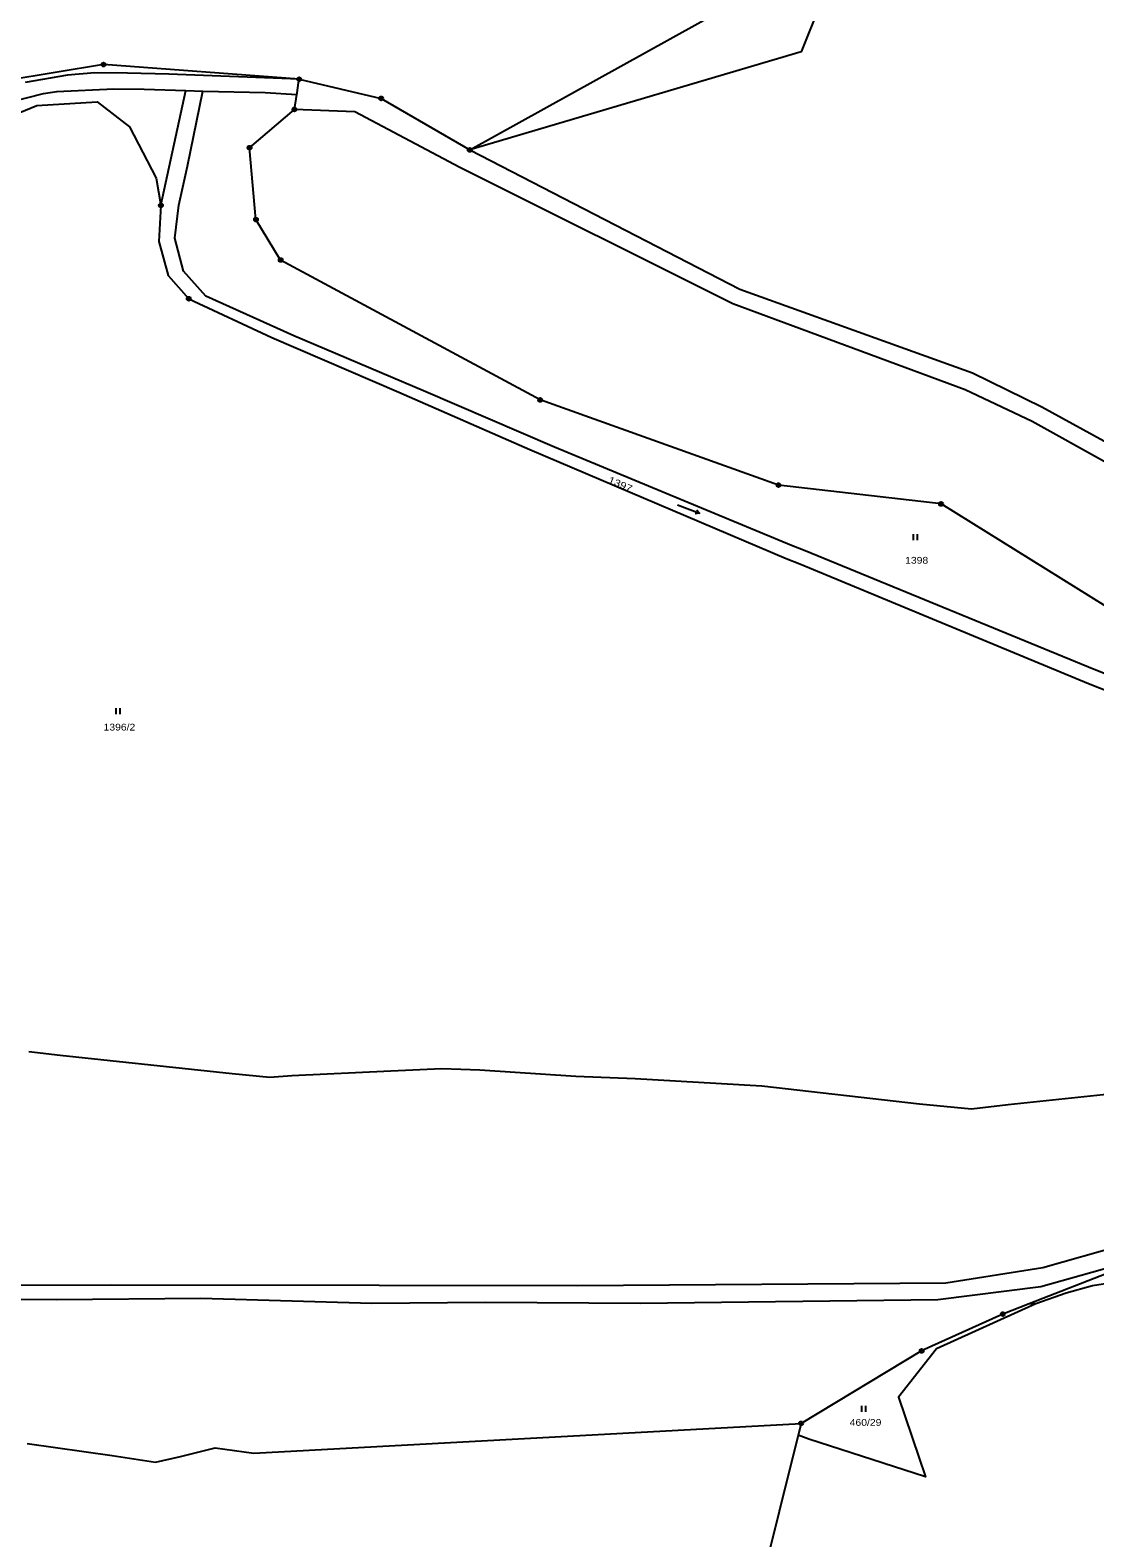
# Model space of a CAD drawing. Extents: x -872229 to -869198, y -1075981 to -1074329.
# Drawn here: x -870040 to -869771.9, y -1075317.7 to -1074938.2 of the extents above; entities that cross this region are included whole.
import ezdxf

# ---------------------------------------------------------------- set-up
doc = ezdxf.new("R2010")
doc.units = 0
doc.header["$LTSCALE"] = 0.68
for name, color, linetype, lineweight in [('1', 7, 'Continuous', 25), ('3', 7, 'Continuous', 25), ('8', 7, 'Continuous', 25)]:
    doc.layers.add(name, color=color, linetype=linetype, lineweight=lineweight)
doc.layers.add('2', color=7, linetype='Continuous')

msp = doc.modelspace()

# ---------------------------------------------------------------- linework, layer by layer
at = {"layer": '1'}
for p, q in [((-870000.81, -1074953.44), (-869996.55, -1074953.58)), ((-869973.47, -1074958.19), (-869972.88, -1074954.43)), ((-869786.75, -1075258.83), (-869788.46, -1075258.83))]:
    msp.add_line(p, q, dxfattribs=at)
for points in [[(-869929.31, -1074968.38), (-869859.5, -1074929.56), (-869836.07, -1074859.72), (-869814.43, -1074830.62), (-869841.11, -1074822.59), (-869856.86, -1074756.63), (-869872.29, -1074734.28)], [(-869776.86, -1074851.73), (-869795.77, -1074853.27), (-869831.49, -1074907.84), (-869845.83, -1074943.67), (-869929.31, -1074968.38)], [(-869972.29, -1074950.57), (-870021.54, -1074946.89), (-870070.32, -1074954.92), (-870080.13, -1074961.97), (-870086.48, -1074985.27), (-870095.97, -1074990.9), (-870107.93, -1074988.38), (-870115.36, -1074981.96)], [(-869972.29, -1074950.57), (-870005.11, -1074949.31), (-870015.47, -1074949.04), (-870023.75, -1074949), (-870030.59, -1074949.58), (-870041.3, -1074951.38)], [(-870192.71, -1075015.36), (-870177.13, -1075014.56), (-870131.91, -1075008.73), (-870095.14, -1075003.44), (-870085.27, -1074997.72), (-870068.68, -1074975.81), (-870058.23, -1074965.32), (-870038.32, -1074957.19), (-870023.13, -1074956.23), (-870015.04, -1074962.59), (-870008.3, -1074975.45), (-870007.09, -1074982.34), (-870000.81, -1074953.44)], [(-870048.94, -1074957.25), (-870036.64, -1074954.16), (-870033.32, -1074953.66), (-870018.94, -1074952.97), (-870011.33, -1074953.07), (-870000.81, -1074953.44)], [(-869650.14, -1075156.59), (-869663.85, -1075147.72), (-869682.43, -1075136.12), (-869690.84, -1075131.53), (-869772.1, -1075099.13), (-869844.86, -1075069.32), (-869848.3, -1075067.94), (-869907.96, -1075043.15), (-869940.96, -1075028.98), (-869973.59, -1075015.13), (-869995.78, -1075005.14), (-870001.42, -1074998.91), (-870003.58, -1074990.56), (-870002.58, -1074982.27), (-870000.39, -1074972.48), (-869996.55, -1074953.58)], [(-869996.55, -1074953.58), (-869980.83, -1074953.94), (-869972.88, -1074954.43)], [(-869972.88, -1074954.43), (-869972.82, -1074954.01), (-869972.43, -1074951.5), (-869972.29, -1074950.57)], [(-869972.29, -1074950.57), (-869951.64, -1074955.4), (-869929.31, -1074968.38)], [(-869646.48, -1075133.71), (-869717.21, -1075097.82), (-869761.54, -1075087.98), (-869810.64, -1075057.49), (-869851.57, -1075052.75), (-869911.59, -1075031.3), (-869976.94, -1074996.08), (-869983.15, -1074985.9), (-869984.78, -1074967.82), (-869973.47, -1074958.19)], [(-869479.66, -1075070.06), (-869480.79, -1075070.33), (-869510.31, -1075083.29), (-869563.58, -1075099.14), (-869607.33, -1075104.27), (-869641.09, -1075105.05), (-869657.9, -1075102.95), (-869677.61, -1075097.87), (-869787.66, -1075036.73), (-869804.59, -1075028.78), (-869863.04, -1075007.07), (-869931.86, -1074972.77), (-869958.29, -1074958.82), (-869973.47, -1074958.19)], [(-869929.31, -1074968.38), (-869861.33, -1075003.43), (-869802.73, -1075024.51), (-869785.27, -1075033.02), (-869675.06, -1075093.42), (-869657.01, -1075098.88), (-869640.84, -1075100.95), (-869607.45, -1075100.23), (-869563.99, -1075095.38), (-869511.48, -1075079.68), (-869481.91, -1075066.7), (-869467.98, -1075063.1), (-869463.59, -1075063.5)], [(-870007.09, -1074982.34), (-870007.65, -1074991.46), (-870005.25, -1074999.97), (-870000.07, -1075005.82), (-869979.18, -1075015.56), (-869947.14, -1075029.34), (-869914.15, -1075043.78), (-869849.68, -1075071.21), (-869846.22, -1075072.58), (-869773.51, -1075102.64), (-869692.27, -1075134.64), (-869683.71, -1075138.39), (-869669.29, -1075147.62), (-869665.53, -1075150.2), (-869650.68, -1075159.97)], [(-869656.67, -1075197.48), (-869676.11, -1075198.92), (-869705.7, -1075200.11), (-869719.96, -1075200.44), (-869741.96, -1075203.08), (-869769.79, -1075206.17), (-869793.73, -1075208.74), (-869802.97, -1075209.8), (-869816.06, -1075208.55), (-869855.81, -1075204.07), (-869887.65, -1075202.22), (-869902.63, -1075201.56), (-869926.76, -1075200.04), (-869936.33, -1075199.65), (-869949.18, -1075200.24), (-869974.1, -1075201.42), (-869979.65, -1075201.82), (-869989.18, -1075200.96), (-870032.43, -1075196.35), (-870040.36, -1075195.42)], [(-870385.12, -1075316.07), (-870355.23, -1075301.89), (-870314.21, -1075282.93), (-870280.58, -1075266.36), (-870265.86, -1075261.9), (-870249.15, -1075258.69), (-870230, -1075254.57), (-870219.5, -1075254.87), (-870207.6, -1075253.65), (-870190, -1075251.81), (-870178.96, -1075255.5), (-870167.23, -1075255.17), (-870141.46, -1075254.46), (-870092.41, -1075254.3), (-870019.81, -1075254.06), (-869952.16, -1075254.08), (-869902.23, -1075254.21), (-869809.43, -1075253.56), (-869784.98, -1075249.67), (-869765.49, -1075244.15), (-869696.7, -1075225.43), (-869659.27, -1075213.75)], [(-870086.74, -1075257.68), (-870033.35, -1075257.7), (-869997.08, -1075257.38), (-869953.96, -1075258.61), (-869925.38, -1075258.43), (-869886.31, -1075258.63), (-869811.48, -1075257.76), (-869785.54, -1075254.45), (-869749.68, -1075244.36), (-869718.38, -1075235.81), (-869677.56, -1075222.96), (-869659.87, -1075217.53)], [(-869709.56, -1075239.45), (-869765.65, -1075249.96), (-869788.46, -1075258.83)], [(-869684.1, -1075246.72), (-869694.41, -1075248.14), (-869706.94, -1075248.13), (-869726.28, -1075244.45), (-869746.39, -1075250.29), (-869772.5, -1075254.32), (-869779.17, -1075256.14), (-869786.75, -1075258.83)], [(-869786.75, -1075258.83), (-869811.82, -1075270.12), (-869821.36, -1075282.34), (-869814.57, -1075302.35), (-869843.97, -1075292.89), (-869846.6, -1075291.84), (-869856.2, -1075330.32)], [(-869788.46, -1075258.83), (-869795.08, -1075261.41), (-869815.52, -1075270.65), (-869845.88, -1075288.92), (-869846.6, -1075291.84)], [(-870040.81, -1075293.97), (-870019.39, -1075297.01), (-870008.45, -1075298.66), (-870002.2, -1075297.21), (-869993.42, -1075295.03), (-869983.72, -1075296.42), (-869845.88, -1075288.92)]]:
    msp.add_lwpolyline(points, dxfattribs=at)
at = {"layer": '3'}
for p, q in [((-869871.436, -1075059.839), (-869872.528, -1075059.957)), ((-869817.551, -1075066.62), (-869817.551, -1075065.12)), ((-869816.55, -1075066.62), (-869816.55, -1075065.12)), ((-870018.391, -1075110.42), (-870018.391, -1075108.92)), ((-870017.39, -1075110.42), (-870017.39, -1075108.92)), ((-869830.621, -1075286.01), (-869830.621, -1075284.51)), ((-869829.62, -1075286.01), (-869829.62, -1075284.51))]:
    msp.add_line(p, q, dxfattribs=at)
msp.add_lwpolyline([(-869877.038, -1075057.689), (-869871.436, -1075059.839), (-869872.169, -1075059.021)], dxfattribs=at)
at = {"layer": '8'}
for centre, radius in [((-870021.54, -1074946.8899), 0.5), ((-870021.54, -1074946.8899), 0.0303), ((-869972.29, -1074950.5699), 0.5), ((-869972.29, -1074950.5699), 0.0303), ((-869973.47, -1074958.1899), 0.5), ((-869951.64, -1074955.3999), 0.5), ((-869951.64, -1074955.3999), 0.0303), ((-869973.47, -1074958.1899), 0.0303), ((-869984.78, -1074967.8199), 0.5), ((-869984.78, -1074967.8199), 0.0303), ((-869929.31, -1074968.3799), 0.5), ((-869929.31, -1074968.3799), 0.0303), ((-870007.09, -1074982.3399), 0.5), ((-870007.09, -1074982.3399), 0.0303), ((-869983.15, -1074985.8999), 0.5), ((-869983.15, -1074985.8999), 0.0303), ((-869976.94, -1074996.0799), 0.5), ((-869976.94, -1074996.0799), 0.0303), ((-870000.07, -1075005.8199), 0.5), ((-870000.07, -1075005.8199), 0.0303), ((-869911.59, -1075031.2999), 0.5), ((-869911.59, -1075031.2999), 0.0303), ((-869851.57, -1075052.7499), 0.5), ((-869851.57, -1075052.7499), 0.0303), ((-869810.64, -1075057.4899), 0.5), ((-869810.64, -1075057.4899), 0.0303), ((-869795.08, -1075261.4099), 0.5), ((-869795.08, -1075261.4099), 0.0303), ((-869815.52, -1075270.6499), 0.5), ((-869815.52, -1075270.6499), 0.0303), ((-869845.88, -1075288.9199), 0.5), ((-869845.88, -1075288.9199), 0.0303)]:
    msp.add_circle(centre, radius, dxfattribs=at)

# ---------------------------------------------------------------- texts
at = {"layer": '2', "width": 1.25}
msp.add_text('1397', height=1.7, rotation=337, dxfattribs=at).set_placement((-869894.632, -1075052.062))
at = {"layer": '2', "width": 1.15}
for s, p in [('1398', (-869819.69, -1075072.51)), ('1396/2', (-870021.54, -1075114.51)), ('460/29', (-869833.65, -1075289.52))]:
    msp.add_text(s, height=1.7, dxfattribs=at).set_placement(p)

doc.saveas('drawing.dxf')
